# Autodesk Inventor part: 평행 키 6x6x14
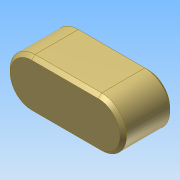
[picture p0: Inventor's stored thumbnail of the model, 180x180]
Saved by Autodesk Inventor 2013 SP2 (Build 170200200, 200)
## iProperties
Created: 2025-09
Part Number: 평행 키 6x6x14
Material: Generic
Document SubType Name: Modeling
Designer: a
Density: 1 g/cm^3
Author: a
변환 표준: STEP AP214IS
전처리기: Build: 200, Release: 2013 SP2 Update 6 - Date: Thu 07/17/2014
전송 단위: 밀리미터
불확실성: 0.01
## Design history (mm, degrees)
node "평행 키 6x6x141"
body "Solid1"
node "기준1"
